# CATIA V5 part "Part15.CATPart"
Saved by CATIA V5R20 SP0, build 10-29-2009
Part number: socket countersunk head screw_din_DIN 7991 - M6 x 16 --- 16N
Revision: ANY
Definition: UNKNOWN
Nomenclature: socket countersunk head screw_din_DIN 7991 - M6 x 16 --- 16N
Source: Unknown
Bounding box of the stored display mesh (mm): x 0 to 16, y -5.785 to 5.785, z -5.785 to 5.785
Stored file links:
  C:\Users\Utente\Desktop\IO LAVORO\3D X SITO CF\CUMSA\3D files GR\GR 222826-15\Part15.CATPart
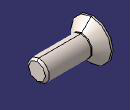
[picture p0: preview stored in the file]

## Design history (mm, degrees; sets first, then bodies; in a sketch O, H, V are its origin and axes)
Body1 "Hex" (main body)
  Solid1: solid without history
